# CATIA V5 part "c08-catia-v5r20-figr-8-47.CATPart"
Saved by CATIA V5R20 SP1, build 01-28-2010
Part number: Part1
Bounding box of the stored display mesh (mm): x -46.99 to 46.99, y -111.421 to 111.421, z 0 to 30
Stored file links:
  D:\v5_r20\psrt_files_downloaded\c08-catia-v5r20-prt\c08-catia-v5r20-figr-8-47.CATPart
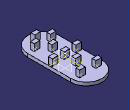
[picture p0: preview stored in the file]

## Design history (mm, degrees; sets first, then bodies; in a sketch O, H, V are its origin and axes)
Body1 (main body)
  Sketch1 on xy-plane, origin (0, 0, 0), H (1, 0, 0), V (0, 1, 0)
    construction line L1 (-46.9897, 64.4313) -> (46.9897, 64.4313)
    line L2 (46.9897, 64.4313) -> (46.9897, -64.4313)
    construction line L3 (46.9897, -64.4313) -> (-46.9897, -64.4313)
    line L4 (-46.9897, -64.4313) -> (-46.9897, 64.4313)
    axis line L5 (46.9897, -64.4313) -> (-46.9897, 64.4313)
    arc A1 centre (0, 64.4313) radius 46.9897 from (-46.9897, 64.4313) to (46.9897, 64.4313) cw
    arc A2 centre (0, -64.4313) radius 46.9897 from (-46.9897, -64.4313) to (46.9897, -64.4313) ccw
    point P7 (0, -111.4211)
    length L3 = 93.9795
    length L2 = 128.8627
    horizontal: L1 H, L3 H
    vertical: L2 V, L4 V
    midpoint: O L5
    tangency: A1 L2, A2 L4
    coincidence: A2 P7, P7 V
  Pad1: profile Sketch1, direction (0, 0, 1), length 10
  Sketch2 on face of Pad1, origin (0, 0, 10), H (1, 0, 0), V (0, 1, 0)
    line L1 (-8.4317, -82.0722) -> (8.3047, -82.0722)
    line L2 (8.3047, -82.0722) -> (8.3047, -93.8638)
    line L3 (8.3047, -93.8638) -> (-8.4317, -93.8638)
    line L4 (-8.4317, -93.8638) -> (-8.4317, -82.0722)
    horizontal: L1 H, L3 H
    vertical: L2 V, L4 V
  Pad2: profile Sketch2, direction (0, 0, 1), length 20
  Sketch3 on face of Pad1, origin (0, 0, 10), H (1, 0, 0), V (0, 1, 0)
    point P1 (-25.1683, -66.0965)
    point P2 (23.8999, -66.0965)
    point P3 (-35.058, 0)
    point P4 (35.3111, 0)
    point P5 (-25.1683, 70.4575)
    point P6 (23.8999, 70.4575)
    point P7 (0, 0)
    point P8 (0, -36.8078)
    point P9 (0, 34.322)
    coincidence: P3 H, P4 H, P7 O, P8 V, P9 V
  UserPattern1: of Pad2, copies 10, at the points of Sketch3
